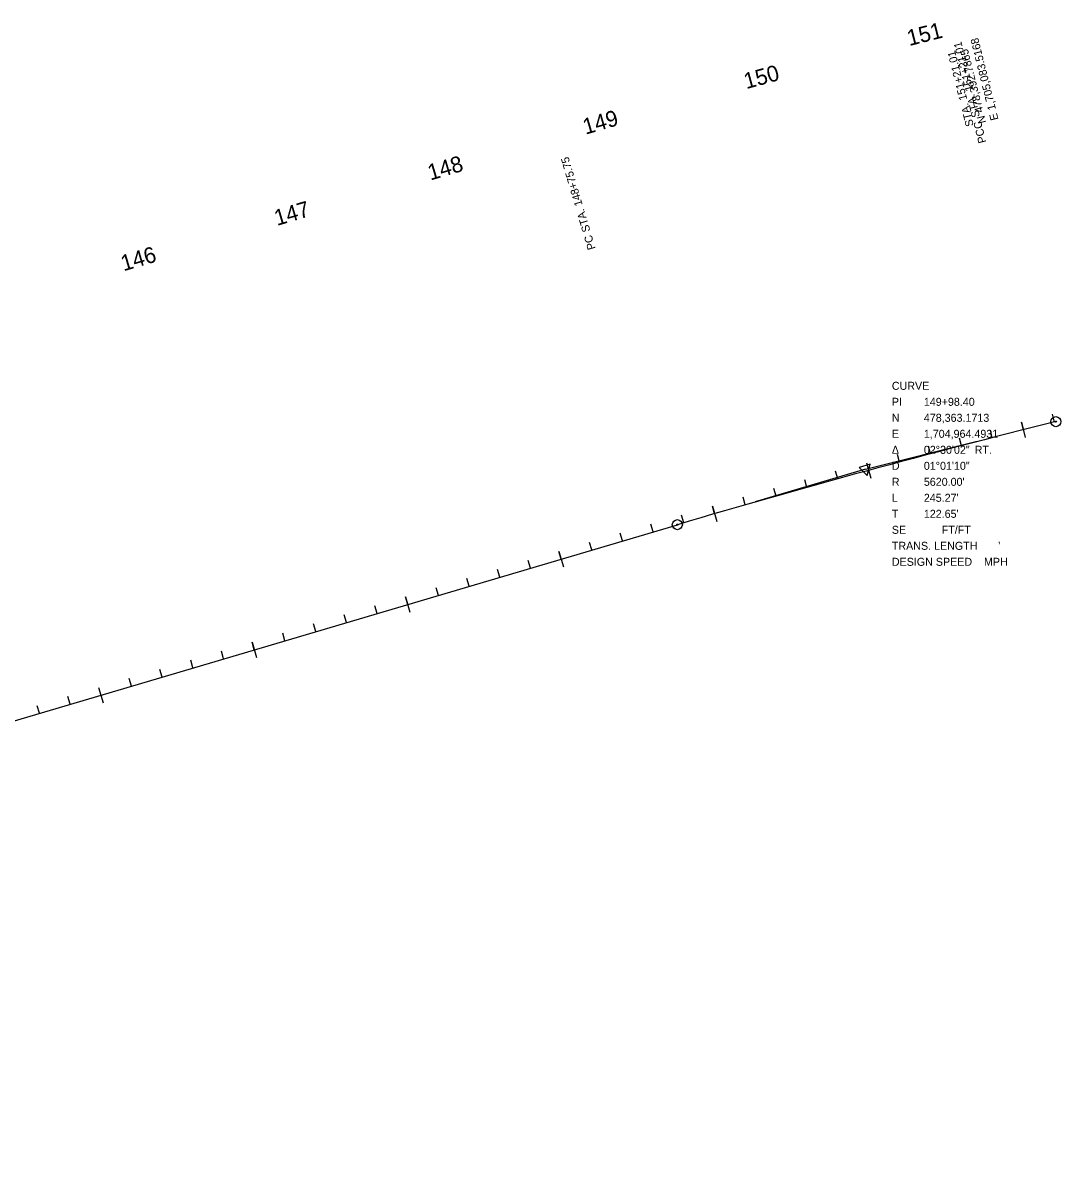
# Model space of a CAD drawing. Extents: x 1699999 to 1705087, y 475568 to 482652.
# Drawn here: x 1704438 to 1705087, y 477922 to 478642 of the extents above; entities that cross this region are included whole.
import ezdxf

# ---------------------------------------------------------------- set-up
doc = ezdxf.new("R2010")
doc.units = 0
for name, color, linetype in [('DES - DTM - Boundary', 7, 'Continuous'), ('DES - DTM - Ground', 7, 'Continuous'), ('DES - DTM - Points - High', 7, 'Continuous'), ('DESIGN - TYPICAL - Guardrail', 7, 'Continuous'), ('TC_Aggregate', 7, 'Continuous')]:
    doc.layers.add(name, color=color, linetype=linetype)

msp = doc.modelspace()

# ---------------------------------------------------------------- linework, layer by layer
at = {"layer": 'DES - DTM - Ground'}
msp.add_line((1703472.49, 477921.97), (1704846.87, 478328.39), dxfattribs=at)
msp.add_arc((1706440.5, 472939.07), 5620, 103.97247, 106.47295, dxfattribs=at)
at = {"layer": 'DES - DTM - Points - High'}
for p, q in [((1705082.53, 478392.54), (1705081.33, 478397.37)), ((1705061.91, 478392.52), (1705064.36, 478382.83)), ((1705024.39, 478377.73), (1705023.14, 478382.55)), ((1705043.75, 478382.74), (1705042.52, 478387.56)), ((1705005.05, 478372.66), (1705003.77, 478377.47)), ((1704965.1, 478367.13), (1704967.72, 478357.48)), ((1704985.72, 478367.52), (1704984.43, 478372.33)), ((1704947.12, 478357.03), (1704945.79, 478361.83)), ((1704927.85, 478351.68), (1704926.51, 478356.47)), ((1704889.36, 478340.77), (1704887.99, 478345.56)), ((1704908.59, 478346.26), (1704907.24, 478351.05)), ((1704868.75, 478340.02), (1704871.55, 478330.42)), ((1704850.95, 478329.6), (1704849.55, 478334.37)), ((1704831.78, 478323.93), (1704830.36, 478328.7)), ((1704793.42, 478312.58), (1704792.01, 478317.36)), ((1704812.6, 478318.26), (1704811.18, 478323.03)), ((1704772.82, 478311.71), (1704775.66, 478302.12)), ((1704755.06, 478301.24), (1704753.65, 478306.02)), ((1704735.88, 478295.57), (1704734.47, 478300.34)), ((1704697.52, 478284.23), (1704696.11, 478289)), ((1704716.7, 478289.9), (1704715.29, 478294.67)), ((1704676.93, 478283.35), (1704679.76, 478273.76)), ((1704659.16, 478272.88), (1704657.75, 478277.66)), ((1704620.81, 478261.54), (1704619.39, 478266.32)), ((1704639.99, 478267.21), (1704638.57, 478271.99)), ((1704601.63, 478255.87), (1704600.22, 478260.64)), ((1704581.03, 478254.99), (1704583.87, 478245.4)), ((1704563.27, 478244.53), (1704561.86, 478249.3)), ((1704524.91, 478233.18), (1704523.5, 478237.96)), ((1704544.09, 478238.85), (1704542.68, 478243.63)), ((1704505.73, 478227.51), (1704504.32, 478232.29)), ((1704485.14, 478226.64), (1704487.97, 478217.05)), ((1704467.37, 478216.17), (1704465.96, 478220.94)), ((1704448.2, 478210.5), (1704446.78, 478215.27))]:
    msp.add_line(p, q, dxfattribs=at)
at = {"layer": 'DESIGN - TYPICAL - Guardrail'}
for p, q in [((1705063.14, 478387.67), (1705061.92, 478392.5)), ((1704965.1, 478367.13), (1704967.73, 478357.46)), ((1704870.15, 478335.22), (1704868.76, 478340)), ((1704774.24, 478306.91), (1704772.83, 478311.69)), ((1704678.34, 478278.55), (1704676.93, 478283.33)), ((1704582.45, 478250.2), (1704581.04, 478254.97)), ((1704485.14, 478226.64), (1704487.98, 478217.03))]:
    msp.add_line(p, q, dxfattribs=at)
for centre, radius in [((1705083.52, 478392.79), 3.14), ((1705083.52, 478392.79), 0.33), ((1704846.87, 478328.39), 3.14), ((1704846.87, 478328.39), 0.33)]:
    msp.add_circle(centre, radius, dxfattribs=at)
at = {"layer": 'TC_Aggregate'}
for q in [(1705034.36, 478380.56), (1704895.45, 478342.75), (1704964.49, 478363.17)]:
    msp.add_line((1704964.49, 478363.17), q, dxfattribs=at)
msp.add_lwpolyline([(1704965.58, 478359.16), (1704967.42, 478366.12), (1704960.47, 478364.23)], close=True, dxfattribs=at)

# ---------------------------------------------------------------- texts
at = {"layer": 'DES - DTM - Boundary'}
for s, rotation, p in [('151+21.01', 103.97247, (1705031.96, 478599.98)), (' STA. ', 103.97247, (1705036.51, 478581.72)), ('PCC', 103.97247, (1705040.05, 478567.46)), ('148+75.75', 106.47295, (1704787.76, 478528.32)), (' STA. ', 106.47295, (1704793.09, 478510.27)), ('PC', 106.47295, (1704795.83, 478501))]:
    msp.add_text(s, height=4.98, rotation=rotation, dxfattribs=at).set_placement(p)
for s, p in [('CURVE    ', (1704980.95, 478412.69)), ('PI', (1704980.95, 478402.69)), ('149+98.40', (1705000.95, 478402.69)), ('N', (1704980.95, 478392.69)), ('478,363.1713', (1705000.95, 478392.69)), ('E', (1704980.95, 478382.69)), ('1,704,964.4931', (1705000.95, 478382.69)), ('Δ', (1704980.95, 478372.69)), ('02°30\'02"', (1705000.95, 478372.69)), (' RT.', (1705030.86, 478372.69)), ('D', (1704980.95, 478362.69)), ('01°01\'10"', (1705000.95, 478362.69)), ('R', (1704980.95, 478352.69)), ("5620.00'", (1705000.95, 478352.69)), ('L', (1704980.95, 478342.69)), ("245.27'", (1705000.95, 478342.69)), ('T', (1704980.95, 478332.69)), ("122.65'", (1705000.95, 478332.69)), ('SE', (1704980.95, 478322.69)), ('      FT/FT', (1705000.95, 478322.69)), ("TRANS. LENGTH       '", (1704980.95, 478312.69)), ('DESIGN SPEED    MPH', (1704980.95, 478302.69))]:
    msp.add_text(s, height=5, dxfattribs=at).set_placement(p)
at = {"layer": 'DES - DTM - Points - High'}
for s, rotation, p in [('151', 14.18669, (1704991.86, 478627.52)), ('150', 15.20618, (1704889.96, 478600.6)), ('149', 16.22568, (1704789.45, 478572.1)), ('148', 16.47351, (1704692.51, 478543.45)), ('147', 16.47351, (1704596.63, 478515.09)), ('146', 16.47351, (1704500.73, 478486.73))]:
    msp.add_text(s, height=9.96, rotation=rotation, dxfattribs=at).set_placement(p)
at = {"layer": 'DESIGN - TYPICAL - Guardrail'}
msp.add_text('150', height=9.96, rotation=15.20618, dxfattribs=at).set_placement((1704889.96, 478600.6))
at = {"layer": 'TC_Aggregate'}
for s, p in [('1,705,083.5168', (1705046.05, 478588.09)), ('151+21.01', (1705028.1, 478594.25)), ('478,392.7865', (1705038.23, 478586.54)), ('STA. ', (1705032.17, 478577.87)), ('N ', (1705039.91, 478579.79)), ('E ', (1705047.64, 478581.71))]:
    msp.add_text(s, height=4.98, rotation=103.97247, dxfattribs=at).set_placement(p)

doc.saveas('drawing.dxf')
